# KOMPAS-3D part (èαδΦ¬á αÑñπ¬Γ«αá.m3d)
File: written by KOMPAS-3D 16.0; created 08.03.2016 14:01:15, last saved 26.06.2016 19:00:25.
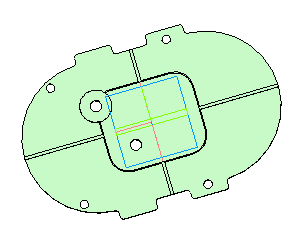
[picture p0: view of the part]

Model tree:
1. Эскиз:1
2. Операция выдавливания:1
     Расстояние 1 = 2
3. Эскиз:2
4. Вырезать элемент выдавливания:1
     Расстояние 1 = 10
5. Скругление:1
     Радиус = 2
6. Скругление:2
     Радиус = 2
7. Эскиз:3
8. Операция выдавливания:2
     Расстояние 1 = 1
9. Эскиз:5
10. Операция выдавливания:4
     Расстояние 1 = 2
11. Эскиз:6
12. Вырезать элемент выдавливания:2
     Расстояние 1 = 10
13. Фаска:2
     Угол = 45; Длина 1 = 1; Длина 2 = 1
14. Эскиз:7
15. Операция выдавливания:5
     Расстояние 1 = 1
16. Операция выдавливания:6
     Расстояние 1 = 2
17. Эскиз:8
18. Вырезать элемент выдавливания:3
     Расстояние 1 = 2
19. Эскиз:9
20. Операция выдавливания:7
     Расстояние 1 = 2
21. Эскиз:10
22. Вырезать элемент выдавливания:4
     Расстояние 1 = 42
